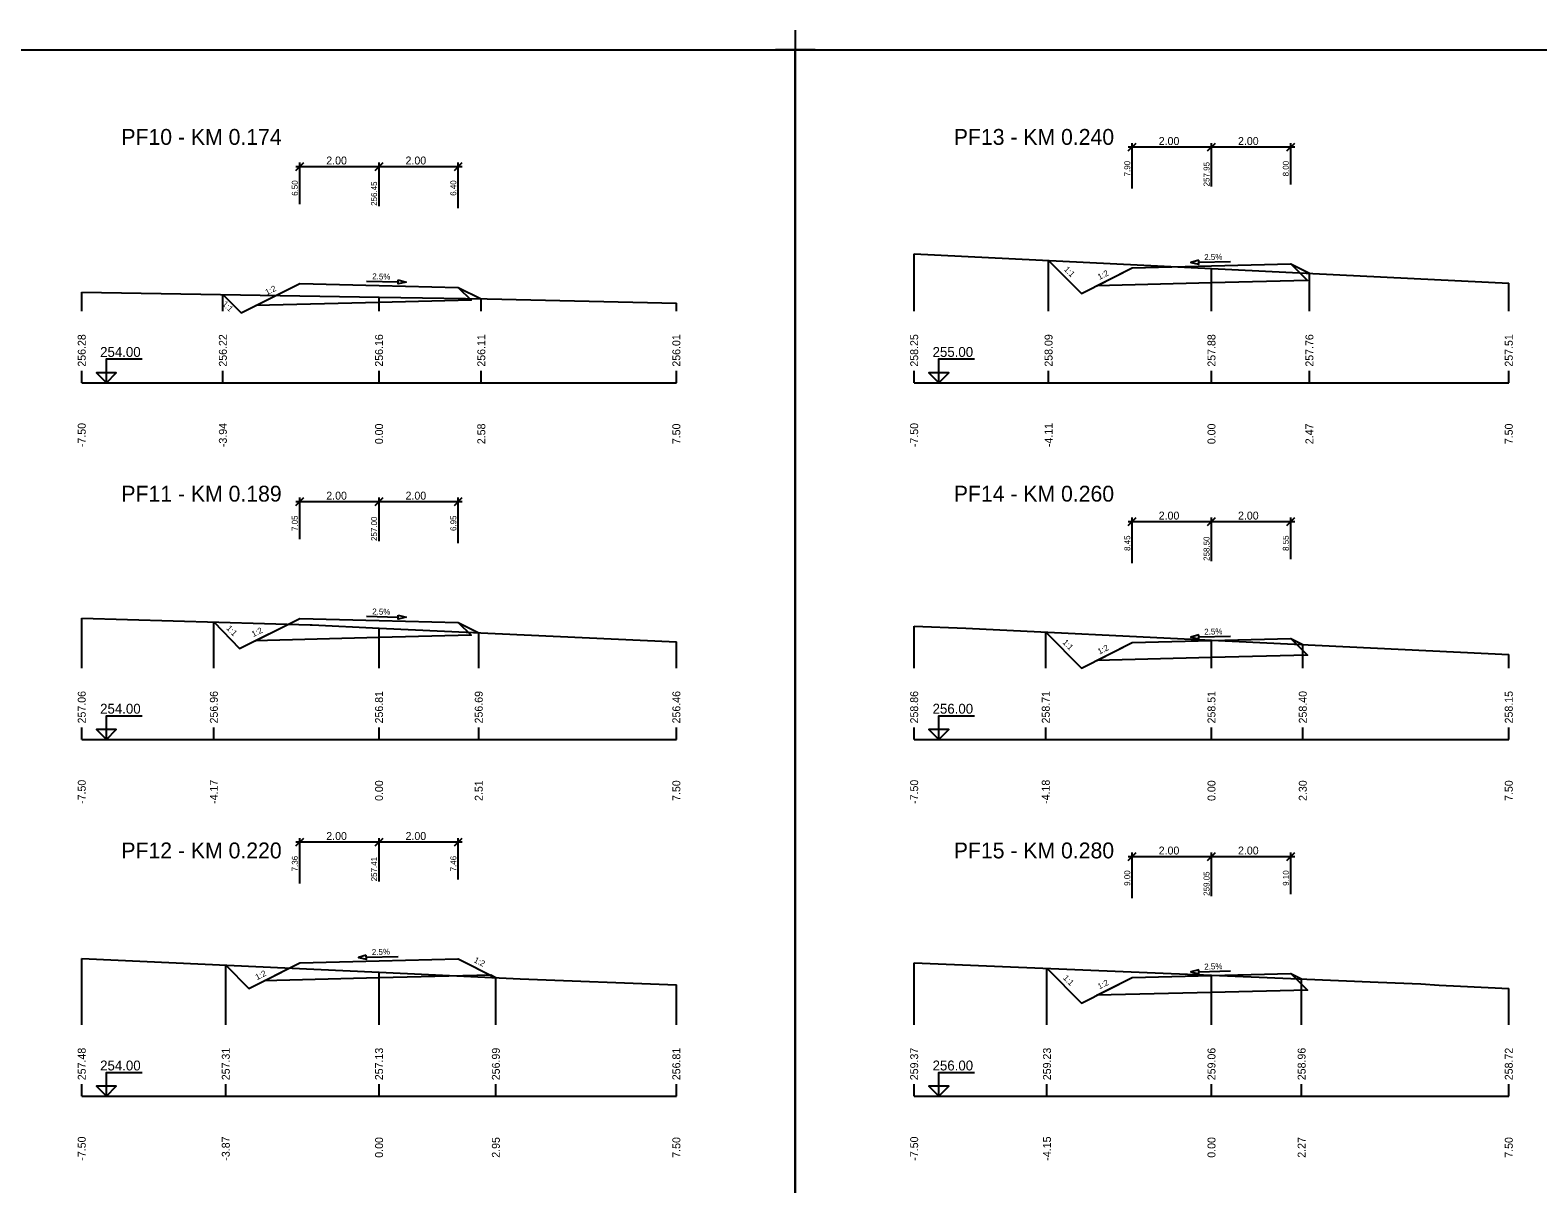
# Model space of a CAD drawing. Extents: x -1895 to 2525, y -19 to 585.
# Drawn here: x -1243 to -862.6, y 293.9 to 584.9 of the extents above; entities that cross this region are included whole.
import ezdxf

# ---------------------------------------------------------------- set-up
doc = ezdxf.new("R2010")
doc.units = 0
for name, color, linetype in [('KOTA', 7, 'Continuous'), ('KOTA_DELKY', 7, 'Continuous'), ('KOTA_DELKY_CONT', 7, 'Continuous'), ('NS_TELESO_VOZOVKY', 7, 'Continuous'), ('NS_V_PF', 7, 'Continuous'), ('REZY_PF_PUVODNI', 7, 'Continuous'), ('SESTAVY_REZU_PF', 7, 'Continuous'), ('SKLON', 7, 'Continuous'), ('SVK', 7, 'Continuous')]:
    doc.layers.add(name, color=color, linetype=linetype)

msp = doc.modelspace()

# ---------------------------------------------------------------- linework, layer by layer
for p, q in [((-1049.95, 584.93), (-1049.95, 574.93)), ((-1049.95, 584.93), (-1049.95, 574.93)), ((-1044.95, 579.93), (-1054.95, 579.93)), ((-1044.95, 579.93), (-1054.95, 579.93))]:
    msp.add_line(p, q)
for points in [[(-1259.95, 579.93), (-1049.95, 579.93), (-1049.95, 282.93), (-1259.95, 282.93)], [(-1049.95, 579.93), (-839.95, 579.93), (-839.95, 282.93), (-1049.95, 282.93)]]:
    msp.add_lwpolyline(points, close=True)
at = {"layer": 'KOTA'}
for points in [[(-1223.73, 498.5), (-1226.23, 498.5), (-1223.73, 496), (-1223.73, 502), (-1214.73, 502)], [(-1223.73, 496), (-1221.23, 498.5), (-1223.73, 498.5)], [(-1013.73, 498.5), (-1016.23, 498.5), (-1013.73, 496), (-1013.73, 502), (-1004.73, 502)], [(-1013.73, 496), (-1011.23, 498.5), (-1013.73, 498.5)], [(-1223.73, 408.5), (-1226.23, 408.5), (-1223.73, 406), (-1223.73, 412), (-1214.73, 412)], [(-1013.73, 408.5), (-1016.23, 408.5), (-1013.73, 406), (-1013.73, 412), (-1004.73, 412)], [(-1223.73, 406), (-1221.23, 408.5), (-1223.73, 408.5)], [(-1013.73, 406), (-1011.23, 408.5), (-1013.73, 408.5)], [(-1223.73, 318.5), (-1226.23, 318.5), (-1223.73, 316), (-1223.73, 322), (-1214.73, 322)], [(-1013.73, 318.5), (-1016.23, 318.5), (-1013.73, 316), (-1013.73, 322), (-1004.73, 322)], [(-1223.73, 316), (-1221.23, 318.5), (-1223.73, 318.5)], [(-1013.73, 316), (-1011.23, 318.5), (-1013.73, 318.5)]]:
    msp.add_lwpolyline(points, dxfattribs=at)
at = {"layer": 'KOTA_DELKY'}
for points in [[(-965.95, 554.46), (-963.95, 556.46)], [(-965.95, 555.46), (-943.95, 555.46)], [(-964.95, 544.96), (-964.95, 556.46)], [(-945.95, 554.46), (-943.95, 556.46)], [(-945.95, 554.46), (-943.95, 556.46)], [(-945.95, 555.46), (-923.95, 555.46)], [(-944.95, 545.46), (-944.95, 556.46)], [(-944.95, 545.46), (-944.95, 556.46)], [(-925.95, 554.46), (-923.95, 556.46)], [(-924.95, 545.96), (-924.95, 556.46)], [(-1175.95, 549.55), (-1173.95, 551.55)], [(-1174.95, 541.05), (-1174.95, 551.55)], [(-1155.95, 549.55), (-1153.95, 551.55)], [(-1155.95, 549.55), (-1153.95, 551.55)], [(-1154.95, 540.55), (-1154.95, 551.55)], [(-1154.95, 540.55), (-1154.95, 551.55)], [(-1135.95, 549.55), (-1133.95, 551.55)], [(-1134.95, 540.05), (-1134.95, 551.55)], [(-1175.95, 550.55), (-1153.95, 550.55)], [(-1155.95, 550.55), (-1133.95, 550.55)], [(-1175.95, 465), (-1173.95, 467)], [(-1175.95, 466), (-1153.95, 466)], [(-1174.95, 456.5), (-1174.95, 467)], [(-1155.95, 465), (-1153.95, 467)], [(-1155.95, 465), (-1153.95, 467)], [(-1155.95, 466), (-1133.95, 466)], [(-1154.95, 456), (-1154.95, 467)], [(-1154.95, 456), (-1154.95, 467)], [(-1135.95, 465), (-1133.95, 467)], [(-1134.95, 455.5), (-1134.95, 467)], [(-965.95, 459.97), (-963.95, 461.97)], [(-965.95, 460.97), (-943.95, 460.97)], [(-964.95, 450.47), (-964.95, 461.97)], [(-945.95, 459.97), (-943.95, 461.97)], [(-945.95, 459.97), (-943.95, 461.97)], [(-945.95, 460.97), (-923.95, 460.97)], [(-944.95, 450.97), (-944.95, 461.97)], [(-944.95, 450.97), (-944.95, 461.97)], [(-925.95, 459.97), (-923.95, 461.97)], [(-924.95, 451.47), (-924.95, 461.97)], [(-1175.95, 379.14), (-1173.95, 381.14)], [(-1174.95, 369.64), (-1174.95, 381.14)], [(-1155.95, 379.14), (-1153.95, 381.14)], [(-1155.95, 379.14), (-1153.95, 381.14)], [(-1154.95, 370.14), (-1154.95, 381.14)], [(-1154.95, 370.14), (-1154.95, 381.14)], [(-1135.95, 379.14), (-1133.95, 381.14)], [(-1134.95, 370.64), (-1134.95, 381.14)], [(-1175.95, 380.14), (-1153.95, 380.14)], [(-1155.95, 380.14), (-1133.95, 380.14)], [(-965.95, 375.48), (-963.95, 377.48)], [(-964.95, 365.98), (-964.95, 377.48)], [(-945.95, 375.48), (-943.95, 377.48)], [(-945.95, 375.48), (-943.95, 377.48)], [(-944.95, 366.48), (-944.95, 377.48)], [(-944.95, 366.48), (-944.95, 377.48)], [(-925.95, 375.48), (-923.95, 377.48)], [(-924.95, 366.98), (-924.95, 377.48)], [(-965.95, 376.48), (-943.95, 376.48)], [(-945.95, 376.48), (-923.95, 376.48)]]:
    msp.add_lwpolyline(points, dxfattribs=at)
at = {"layer": 'NS_TELESO_VOZOVKY'}
for points in [[(-944.95, 525.46), (-924.95, 525.96), (-924.95, 525.96), (-920.75, 521.76), (-944.95, 521.16), (-973.89, 520.43), (-964.95, 524.96), (-964.95, 524.96), (-944.95, 525.46)], [(-1154.95, 520.55), (-1134.95, 520.05), (-1134.95, 520.05), (-1131.73, 516.83), (-1154.95, 516.25), (-1186.05, 515.47), (-1174.95, 521.05), (-1174.95, 521.05), (-1154.95, 520.55)], [(-1154.95, 436), (-1134.95, 435.5), (-1134.95, 435.5), (-1131.73, 432.28), (-1154.95, 431.7), (-1186.18, 430.92), (-1174.95, 436.5), (-1174.95, 436.5), (-1154.95, 436)], [(-944.95, 430.97), (-924.95, 431.47), (-924.95, 431.47), (-920.75, 427.27), (-944.95, 426.67), (-973.89, 425.95), (-964.95, 430.47), (-964.95, 430.47), (-944.95, 430.97)], [(-1154.95, 350.14), (-1134.95, 350.64), (-1134.95, 350.64), (-1125.48, 345.9), (-1126.76, 346.55), (-1154.95, 345.84), (-1183.89, 345.12), (-1174.95, 349.64), (-1174.95, 349.64), (-1154.95, 350.14)], [(-944.95, 346.48), (-924.95, 346.98), (-924.95, 346.98), (-920.75, 342.79), (-944.95, 342.18), (-973.89, 341.46), (-964.95, 345.98), (-964.95, 345.98), (-944.95, 346.48)]]:
    msp.add_lwpolyline(points, dxfattribs=at)
at = {"layer": 'NS_V_PF'}
for points in [[(-986.05, 526.86), (-977.76, 518.48), (-964.95, 524.96), (-964.95, 524.96), (-944.95, 525.46), (-924.95, 525.96), (-924.95, 525.96), (-920.25, 523.61)], [(-1194.35, 518.22), (-1189.7, 513.64), (-1174.95, 521.05), (-1174.95, 521.05), (-1154.95, 520.55), (-1134.95, 520.05), (-1134.95, 520.05), (-1129.15, 517.15)], [(-1196.62, 435.64), (-1190.14, 428.95), (-1174.95, 436.5), (-1174.95, 436.5), (-1154.95, 436), (-1134.95, 435.5), (-1134.95, 435.5), (-1129.8, 432.93)], [(-986.75, 433.08), (-977.76, 423.99), (-964.95, 430.47), (-964.95, 430.47), (-944.95, 430.97), (-924.95, 431.47), (-924.95, 431.47), (-921.92, 429.95)], [(-1193.61, 349.08), (-1187.76, 343.16), (-1174.95, 349.64), (-1174.95, 349.64), (-1154.95, 350.14), (-1134.95, 350.64), (-1134.95, 350.64), (-1125.48, 345.9)], [(-986.45, 348.29), (-977.76, 339.51), (-964.95, 345.98), (-964.95, 345.98), (-944.95, 346.48), (-924.95, 346.98), (-924.95, 346.98), (-922.21, 345.61)]]:
    msp.add_lwpolyline(points, dxfattribs=at)
at = {"layer": 'REZY_PF_PUVODNI'}
for points in [[(-1019.95, 528.54), (-944.95, 524.83), (-869.95, 521.12)], [(-1229.95, 518.8), (-1154.95, 517.57), (-1127.67, 517.12), (-1079.95, 516.09)], [(-1229.95, 436.62), (-1172.3, 434.92), (-1171.8, 434.9), (-1154.95, 434.11), (-1079.95, 430.59)], [(-1019.95, 434.59), (-1006.88, 434.05), (-944.95, 431.06), (-869.95, 427.45)], [(-1229.95, 350.78), (-1154.95, 347.28), (-1119.36, 345.62), (-1079.95, 344.08)], [(-1019.95, 349.68), (-944.95, 346.56), (-902.87, 344.81), (-892.13, 344.32), (-887.48, 343.99), (-882.14, 343.78), (-869.95, 343.16)]]:
    msp.add_lwpolyline(points, dxfattribs=at)
at = {"layer": 'SESTAVY_REZU_PF'}
for points in [[(-1229.95, 496), (-1079.95, 496)], [(-1019.95, 496), (-869.95, 496)], [(-1229.95, 406), (-1079.95, 406)], [(-1019.95, 406), (-869.95, 406)], [(-1229.95, 316), (-1079.95, 316)], [(-1019.95, 316), (-869.95, 316)]]:
    msp.add_lwpolyline(points, dxfattribs=at)
at = {"layer": 'SKLON'}
for points in [[(-948.16, 526.88), (-950.15, 526.33), (-948.14, 525.88), (-948.16, 526.88)], [(-948.15, 526.38), (-940.15, 526.58)], [(-1158.1, 521.63), (-1150.1, 521.43)], [(-1150.09, 521.93), (-1148.1, 521.38), (-1150.11, 520.93), (-1150.09, 521.93)], [(-1158.1, 437.08), (-1150.1, 436.88)], [(-1150.09, 437.38), (-1148.1, 436.83), (-1150.11, 436.38), (-1150.09, 437.38)], [(-948.16, 432.39), (-950.15, 431.84), (-948.14, 431.39), (-948.16, 432.39)], [(-948.15, 431.89), (-940.15, 432.09)], [(-1158.16, 351.56), (-1160.15, 351.01), (-1158.14, 350.56), (-1158.16, 351.56)], [(-1158.15, 351.06), (-1150.15, 351.26)], [(-948.16, 347.9), (-950.15, 347.35), (-948.14, 346.9), (-948.16, 347.9)], [(-948.15, 347.4), (-940.15, 347.6)]]:
    msp.add_lwpolyline(points, dxfattribs=at)
at = {"layer": 'SVK'}
for points in [[(-1019.95, 514), (-1019.95, 528.54)], [(-986.05, 514), (-986.05, 526.86)], [(-944.95, 514), (-944.95, 524.83)], [(-920.25, 514), (-920.25, 523.61)], [(-869.95, 514), (-869.95, 521.12)], [(-1229.95, 514), (-1229.95, 518.8)], [(-1194.35, 514), (-1194.35, 518.22)], [(-1154.95, 514), (-1154.95, 517.57)], [(-1129.15, 514), (-1129.15, 517.15)], [(-1079.95, 514), (-1079.95, 516.09)], [(-1229.95, 496), (-1229.95, 499)], [(-1194.35, 496), (-1194.35, 499)], [(-1154.95, 496), (-1154.95, 499)], [(-1129.15, 496), (-1129.15, 499)], [(-1079.95, 496), (-1079.95, 499)], [(-1019.95, 496), (-1019.95, 499)], [(-986.05, 496), (-986.05, 499)], [(-944.95, 496), (-944.95, 499)], [(-920.25, 496), (-920.25, 499)], [(-869.95, 496), (-869.95, 499)], [(-1229.95, 424), (-1229.95, 436.62)], [(-1196.62, 424), (-1196.62, 435.64)], [(-1154.95, 424), (-1154.95, 434.11)], [(-1019.95, 424), (-1019.95, 434.59)], [(-1129.8, 424), (-1129.8, 432.93)], [(-1079.95, 424), (-1079.95, 430.59)], [(-986.75, 424), (-986.75, 433.08)], [(-944.95, 424), (-944.95, 431.06)], [(-921.92, 424), (-921.92, 429.95)], [(-869.95, 424), (-869.95, 427.45)], [(-1229.95, 406), (-1229.95, 409)], [(-1196.62, 406), (-1196.62, 409)], [(-1154.95, 406), (-1154.95, 409)], [(-1129.8, 406), (-1129.8, 409)], [(-1079.95, 406), (-1079.95, 409)], [(-1019.95, 406), (-1019.95, 409)], [(-986.75, 406), (-986.75, 409)], [(-944.95, 406), (-944.95, 409)], [(-921.92, 406), (-921.92, 409)], [(-869.95, 406), (-869.95, 409)], [(-1229.95, 334), (-1229.95, 350.78)], [(-1193.61, 334), (-1193.61, 349.08)], [(-1154.95, 334), (-1154.95, 347.28)], [(-1019.95, 334), (-1019.95, 349.68)], [(-986.45, 334), (-986.45, 348.29)], [(-944.95, 334), (-944.95, 346.56)], [(-1125.48, 334), (-1125.48, 345.9)], [(-1079.95, 334), (-1079.95, 344.08)], [(-922.21, 334), (-922.21, 345.61)], [(-869.95, 334), (-869.95, 343.16)], [(-1229.95, 316), (-1229.95, 319)], [(-1193.61, 316), (-1193.61, 319)], [(-1154.95, 316), (-1154.95, 319)], [(-1125.48, 316), (-1125.48, 319)], [(-1079.95, 316), (-1079.95, 319)], [(-1019.95, 316), (-1019.95, 319)], [(-986.45, 316), (-986.45, 319)], [(-944.95, 316), (-944.95, 319)], [(-922.21, 316), (-922.21, 319)], [(-869.95, 316), (-869.95, 319)]]:
    msp.add_lwpolyline(points, dxfattribs=at)

# ---------------------------------------------------------------- texts
at = {"layer": 'KOTA'}
for s, p in [('254.00', (-1225.31, 502.5)), ('255.00', (-1015.31, 502.5)), ('254.00', (-1225.31, 412.5)), ('256.00', (-1015.31, 412.5)), ('254.00', (-1225.31, 322.5)), ('256.00', (-1015.31, 322.5))]:
    msp.add_text(s, height=2.5, dxfattribs=at).set_placement(p)
at = {"layer": 'KOTA_DELKY'}
for p in [(-958.26, 555.96), (-938.26, 555.96), (-1168.26, 551.05), (-1148.26, 551.05), (-1168.26, 466.5), (-1148.26, 466.5), (-958.26, 461.47), (-938.26, 461.47), (-1168.26, 380.64), (-1148.26, 380.64), (-958.26, 376.98), (-938.26, 376.98)]:
    msp.add_text('2.00', height=2, dxfattribs=at).set_placement(p)
at = {"layer": 'KOTA_DELKY_CONT'}
for s, p in [('7.90', (-965.45, 548.05)), ('257.95', (-945.45, 545.53)), ('8.00', (-925.45, 548.05)), ('6.50', (-1175.45, 543.14)), ('256.45', (-1155.45, 540.62)), ('6.40', (-1135.45, 543.14)), ('7.05', (-1175.45, 458.59)), ('257.00', (-1155.45, 456.08)), ('6.95', (-1135.45, 458.59)), ('8.45', (-965.45, 453.56)), ('258.50', (-945.45, 451.05)), ('8.55', (-925.45, 453.56)), ('7.36', (-1175.45, 372.73)), ('7.46', (-1135.45, 372.73)), ('257.41', (-1155.45, 370.22)), ('9.00', (-965.45, 369.07)), ('9.10', (-925.45, 369.07)), ('259.05', (-945.45, 366.56))]:
    msp.add_text(s, height=1.5, rotation=90, dxfattribs=at).set_placement(p)
at = {"layer": 'SESTAVY_REZU_PF'}
for s, p in [('PF10 - KM 0.174', (-1219.95, 556)), ('PF13 - KM 0.240', (-1009.95, 556)), ('PF11 - KM 0.189', (-1219.95, 466)), ('PF14 - KM 0.260', (-1009.95, 466)), ('PF12 - KM 0.220', (-1219.95, 376)), ('PF15 - KM 0.280', (-1009.95, 376))]:
    msp.add_text(s, height=4, dxfattribs=at).set_placement(p)
at = {"layer": 'SKLON'}
for s, rotation, p in [('1:1', 314.7121, (-982.3, 524.49)), ('2.5%', 1.4321, (-946.75, 526.91)), ('2.5%', 358.5679, (-1156.68, 522.09)), ('1:2', 26.8233, (-973.21, 521.9)), ('1:2', 26.6688, (-1183.21, 518.02)), ('1:1', 315.4346, (-1194.63, 515.73)), ('2.5%', 358.5679, (-1156.68, 437.54)), ('1:1', 314.1179, (-1193.6, 433.95)), ('1:2', 26.4309, (-1186.66, 431.79)), ('2.5%', 1.4321, (-946.75, 432.42)), ('1:1', 314.7121, (-982.65, 430.36)), ('1:2', 26.8233, (-973.21, 427.41)), ('2.5%', 1.4321, (-1156.75, 351.6)), ('1:2', 333.4349, (-1131.18, 349.87)), ('1:2', 26.8233, (-1185.71, 345.26)), ('1:1', 314.7121, (-982.5, 345.72)), ('2.5%', 1.4321, (-946.75, 347.94)), ('1:2', 26.8233, (-973.21, 342.92))]:
    msp.add_text(s, height=1.5, rotation=rotation, dxfattribs=at).set_placement(p)
at = {"layer": 'SVK'}
for s, p in [(' 256.28', (-1228.95, 499.3)), (' 256.22', (-1193.35, 499.3)), (' 256.16', (-1153.95, 499.3)), (' 256.11', (-1128.15, 499.3)), (' 256.01', (-1078.95, 499.3)), (' 258.25', (-1018.95, 499.3)), (' 258.09', (-985.05, 499.3)), (' 257.88', (-943.95, 499.3)), (' 257.76', (-919.25, 499.3)), (' 257.51', (-868.95, 499.3)), (' -7.50', (-1228.95, 479)), (' -3.94', (-1193.35, 479)), ('  0.00', (-1153.95, 479)), ('  2.58', (-1128.15, 479)), ('  7.50', (-1078.95, 479)), (' -7.50', (-1018.95, 479)), (' -4.11', (-985.05, 479)), ('  0.00', (-943.95, 479)), ('  2.47', (-919.25, 479)), ('  7.50', (-868.95, 479)), (' 257.06', (-1228.95, 409.3)), (' 256.96', (-1195.62, 409.3)), (' 256.81', (-1153.95, 409.3)), (' 256.69', (-1128.8, 409.3)), (' 256.46', (-1078.95, 409.3)), (' 258.86', (-1018.95, 409.3)), (' 258.71', (-985.75, 409.3)), (' 258.51', (-943.95, 409.3)), (' 258.40', (-920.92, 409.3)), (' 258.15', (-868.95, 409.3)), (' -7.50', (-1228.95, 389)), (' -4.17', (-1195.62, 389)), ('  0.00', (-1153.95, 389)), ('  2.51', (-1128.8, 389)), ('  7.50', (-1078.95, 389)), (' -7.50', (-1018.95, 389)), (' -4.18', (-985.75, 389)), ('  0.00', (-943.95, 389)), ('  2.30', (-920.92, 389)), ('  7.50', (-868.95, 389)), (' 257.48', (-1228.95, 319.3)), (' 257.31', (-1192.61, 319.3)), (' 257.13', (-1153.95, 319.3)), (' 256.99', (-1124.48, 319.3)), (' 256.81', (-1078.95, 319.3)), (' 259.37', (-1018.95, 319.3)), (' 259.23', (-985.45, 319.3)), (' 259.06', (-943.95, 319.3)), (' 258.96', (-921.21, 319.3)), (' 258.72', (-868.95, 319.3)), (' -7.50', (-1228.95, 299)), (' -3.87', (-1192.61, 299)), ('  0.00', (-1153.95, 299)), ('  2.95', (-1124.48, 299)), ('  7.50', (-1078.95, 299)), (' -7.50', (-1018.95, 299)), (' -4.15', (-985.45, 299)), ('  0.00', (-943.95, 299)), ('  2.27', (-921.21, 299)), ('  7.50', (-868.95, 299))]:
    msp.add_text(s, height=2, rotation=90, dxfattribs=at).set_placement(p)

doc.saveas('drawing.dxf')
